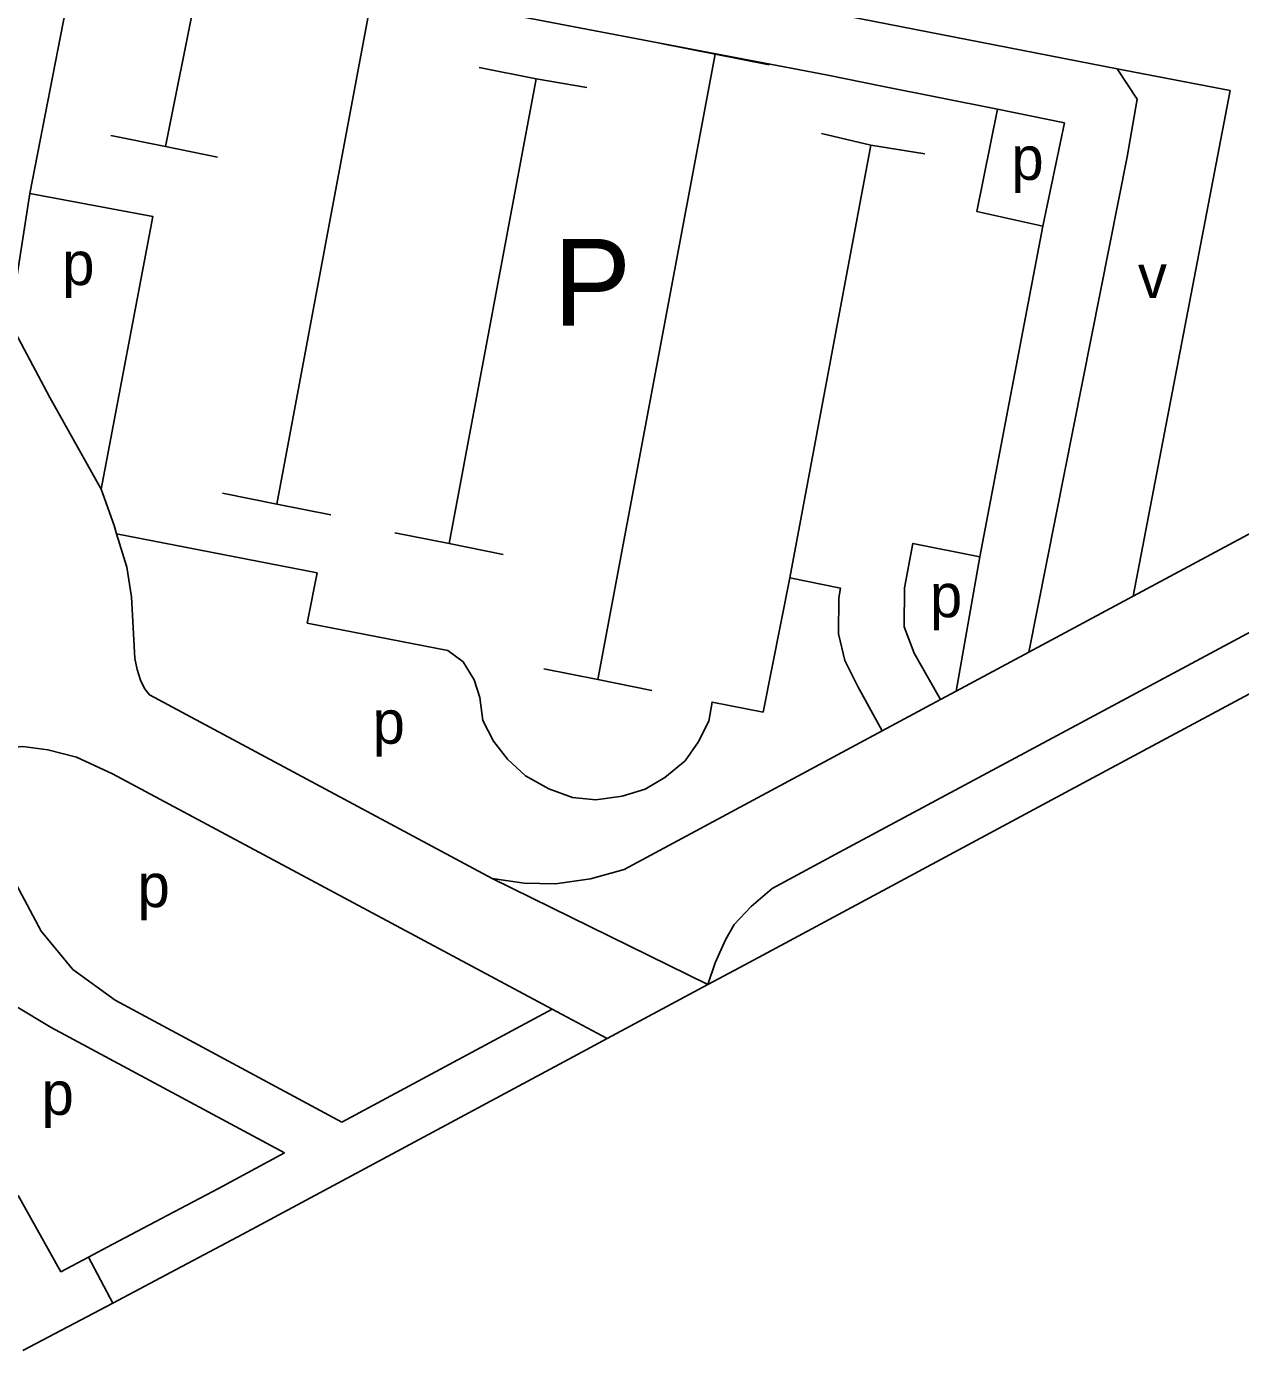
# Model space of a CAD drawing. Extents: x 158356 to 159894, y 383831 to 385260.
# Drawn here: x 159485.7 to 159597.6, y 384327.8 to 384449.8 of the extents above; entities that cross this region are included whole.
import ezdxf

# ---------------------------------------------------------------- set-up
doc = ezdxf.new("R2010")
doc.units = 0
for name, color, linetype in [('BLT_Basislijn', 7, 'Continuous'), ('BLT_Centroide', 7, 'Continuous'), ('BLT_Tekst_parkeren', 7, 'Continuous'), ('BLT_Vlakafsluiter', 7, 'Continuous')]:
    doc.layers.add(name, color=color, linetype=linetype)

msp = doc.modelspace()

# ---------------------------------------------------------------- linework, layer by layer
at = {"layer": 'BLT_Basislijn'}
for p, q in [((159490.74, 384458.44), (159486.07, 384434.39)), ((159559.56, 384445.29), (159490.74, 384458.44)), ((159502.05, 384456.17), (159498.56, 384438.73)), ((159508.8, 384405.78), (159517.7, 384453.25)), ((159544.21, 384448.22), (159549.19, 384447.23)), ((159538.38, 384389.63), (159549.19, 384447.23)), ((159549.19, 384447.23), (159554.16, 384446.23)), ((159527.46, 384445.99), (159532.7, 384444.94)), ((159532.7, 384444.94), (159524.67, 384402.16)), ((159532.7, 384444.94), (159537.36, 384444.14)), ((159559.56, 384445.29), (159564.54, 384444.29)), ((159564.54, 384444.29), (159575.19, 384442.16)), ((159493.51, 384439.72), (159498.56, 384438.73)), ((159558.97, 384439.92), (159563.52, 384438.84)), ((159498.56, 384438.73), (159503.35, 384437.74)), ((159556.05, 384399), (159563.52, 384438.84)), ((159563.52, 384438.84), (159568.49, 384438.06)), ((159484.22, 384422.53), (159486.07, 384434.39)), ((159573.56, 384400.94), (159579.36, 384431.39)), ((159484.22, 384422.53), (159487.89, 384415.61)), ((159492.62, 384407.17), (159487.89, 384415.61)), ((159503.82, 384406.78), (159508.8, 384405.78)), ((159587.68, 384397.31), (159606.38, 384407.34)), ((159508.8, 384405.78), (159513.77, 384404.79)), ((159519.69, 384403.15), (159524.67, 384402.16)), ((159524.67, 384402.16), (159529.65, 384401.16)), ((159561.04, 384373.94), (159610.81, 384400.63)), ((159573.56, 384400.94), (159571.37, 384388.56)), ((159578.09, 384392.16), (159587.68, 384397.31)), ((159571.37, 384388.56), (159578.09, 384392.16)), ((159533.41, 384390.62), (159538.38, 384389.63)), ((159538.38, 384389.63), (159543.36, 384388.63)), ((159569.93, 384387.79), (159571.37, 384388.56)), ((159564.58, 384384.91), (159569.93, 384387.79)), ((159478.78, 384382.01), (159487.1, 384366.47)), ((159509.51, 384346.03), (159488.02, 384357.59)), ((159497.6, 384339.69), (159493.18, 384337.35)), ((159493.7, 384332.21), (159491.46, 384336.44)), ((159485.42, 384327.84), (159493.7, 384332.21))]:
    msp.add_line(p, q, dxfattribs=at)
for points in [[(159490.74, 384458.44), (159492.96, 384460.31), (159496.32, 384461.8), (159500.01, 384462.43), (159505.32, 384461.69), (159586.21, 384445.87)], [(159586.21, 384445.87), (159588.07, 384443.07), (159587.13, 384437.77), (159578.09, 384392.16)], [(159586.21, 384445.87), (159596.62, 384443.87), (159587.68, 384397.31)], [(159575.19, 384442.16), (159573.3, 384432.72), (159579.36, 384431.39)], [(159575.19, 384442.16), (159581.35, 384440.9), (159579.36, 384431.39)], [(159486.07, 384434.39), (159497.38, 384432.28), (159492.62, 384407.17)], [(159492.62, 384407.17), (159493.82, 384403.82), (159494.05, 384403.05)], [(159494.05, 384403.05), (159494.98, 384399.98), (159495.42, 384397.24), (159495.73, 384391.58), (159495.94, 384390.54), (159496.26, 384389.58), (159496.61, 384388.8), (159497.07, 384388.21), (159528.63, 384371.31)], [(159494.05, 384403.05), (159512.51, 384399.45), (159511.61, 384394.83), (159524.57, 384392.31), (159525.98, 384391.25), (159526.98, 384389.61), (159527.52, 384387.98), (159527.78, 384385.85), (159528.78, 384383.96), (159530.07, 384382.29), (159531.71, 384380.77), (159533.85, 384379.57), (159536.03, 384378.78), (159538.2, 384378.56), (159540.63, 384378.89), (159542.73, 384379.53), (159544.56, 384380.62), (159546.42, 384382.13), (159547.61, 384383.85), (159548.6, 384385.79), (159548.9, 384387.56), (159553.6, 384386.64), (159556.05, 384399)], [(159573.56, 384400.94), (159567.4, 384402.16), (159566.62, 384398.09), (159566.61, 384394.48), (159567.53, 384392.05), (159568.81, 384389.78), (159569.93, 384387.79)], [(159556.05, 384399), (159560.73, 384398.06), (159560.58, 384397.16), (159560.55, 384393.84), (159561.14, 384391.38), (159562.32, 384388.98), (159564.58, 384384.91)], [(159563.41, 384369.53), (159581.87, 384379.44), (159613.17, 384396.23)], [(159528.63, 384371.31), (159531.6, 384370.87), (159534.49, 384370.82), (159537.71, 384371.27), (159540.79, 384372.15), (159564.58, 384384.91)], [(159478.78, 384382.01), (159480.69, 384382.71), (159482.75, 384383.26), (159485.41, 384383.46), (159487.73, 384383.17), (159490.35, 384382.47), (159493.66, 384380.96), (159534.17, 384359.27)], [(159473.16, 384374.75), (159477.91, 384365.91), (159481.52, 384361.49), (159488.02, 384357.59)], [(159548.5, 384361.53), (159549.18, 384363.54), (159550.14, 384365.65), (159550.95, 384367.08), (159552.5, 384368.73), (159554.43, 384370.39), (159561.04, 384373.94)], [(159551.92, 384363.37), (159563.41, 384369.53)], [(159514.79, 384348.87), (159493.91, 384360.1), (159490.03, 384362.94), (159487.1, 384366.47)], [(159548.5, 384361.53), (159551.92, 384363.37)], [(159539.23, 384356.56), (159548.5, 384361.53)], [(159514.79, 384348.87), (159534.17, 384359.27)], [(159534.17, 384359.27), (159539.23, 384356.56)], [(159500.06, 384335.58), (159505.67, 384338.55), (159536.52, 384355.1), (159539.23, 384356.56)], [(159497.6, 384339.69), (159503.43, 384342.77), (159509.51, 384346.03)], [(159491.46, 384336.44), (159488.92, 384335.09), (159484.97, 384342.1)], [(159491.46, 384336.44), (159493.18, 384337.35)], [(159493.7, 384332.21), (159500.06, 384335.58)]]:
    msp.add_lwpolyline(points, dxfattribs=at)
at = {"layer": 'BLT_Vlakafsluiter'}
msp.add_line((159548.5, 384361.53), (159528.63, 384371.31), dxfattribs=at)

# ---------------------------------------------------------------- texts
at = {"layer": 'BLT_Centroide'}
for p in [(159576.47, 384435.65), (159489.04, 384425.96), (159568.97, 384395.37), (159517.63, 384383.72), (159495.98, 384368.67), (159487.14, 384349.54)]:
    msp.add_text('p', height=4, dxfattribs=at).set_placement(p)
msp.add_text('v', height=4, rotation=1, dxfattribs=at).set_placement((159588.18, 384424.75))
at = {"layer": 'BLT_Tekst_parkeren'}
msp.add_text('P', height=8, dxfattribs=at).set_placement((159534.3, 384422.21))

doc.saveas('drawing.dxf')
